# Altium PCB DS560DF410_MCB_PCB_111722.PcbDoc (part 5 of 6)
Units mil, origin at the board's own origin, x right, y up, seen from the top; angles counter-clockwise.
Board outline 5500 x 5000 mil, 6 copper layers (Top Layer, L2_GND1, L3_SIG1, L4_PWR1, L5_GND2, Bottom Layer), stack 61.748 mil thick; 297 components, 231 nets, 1236 pads, 998 vias.
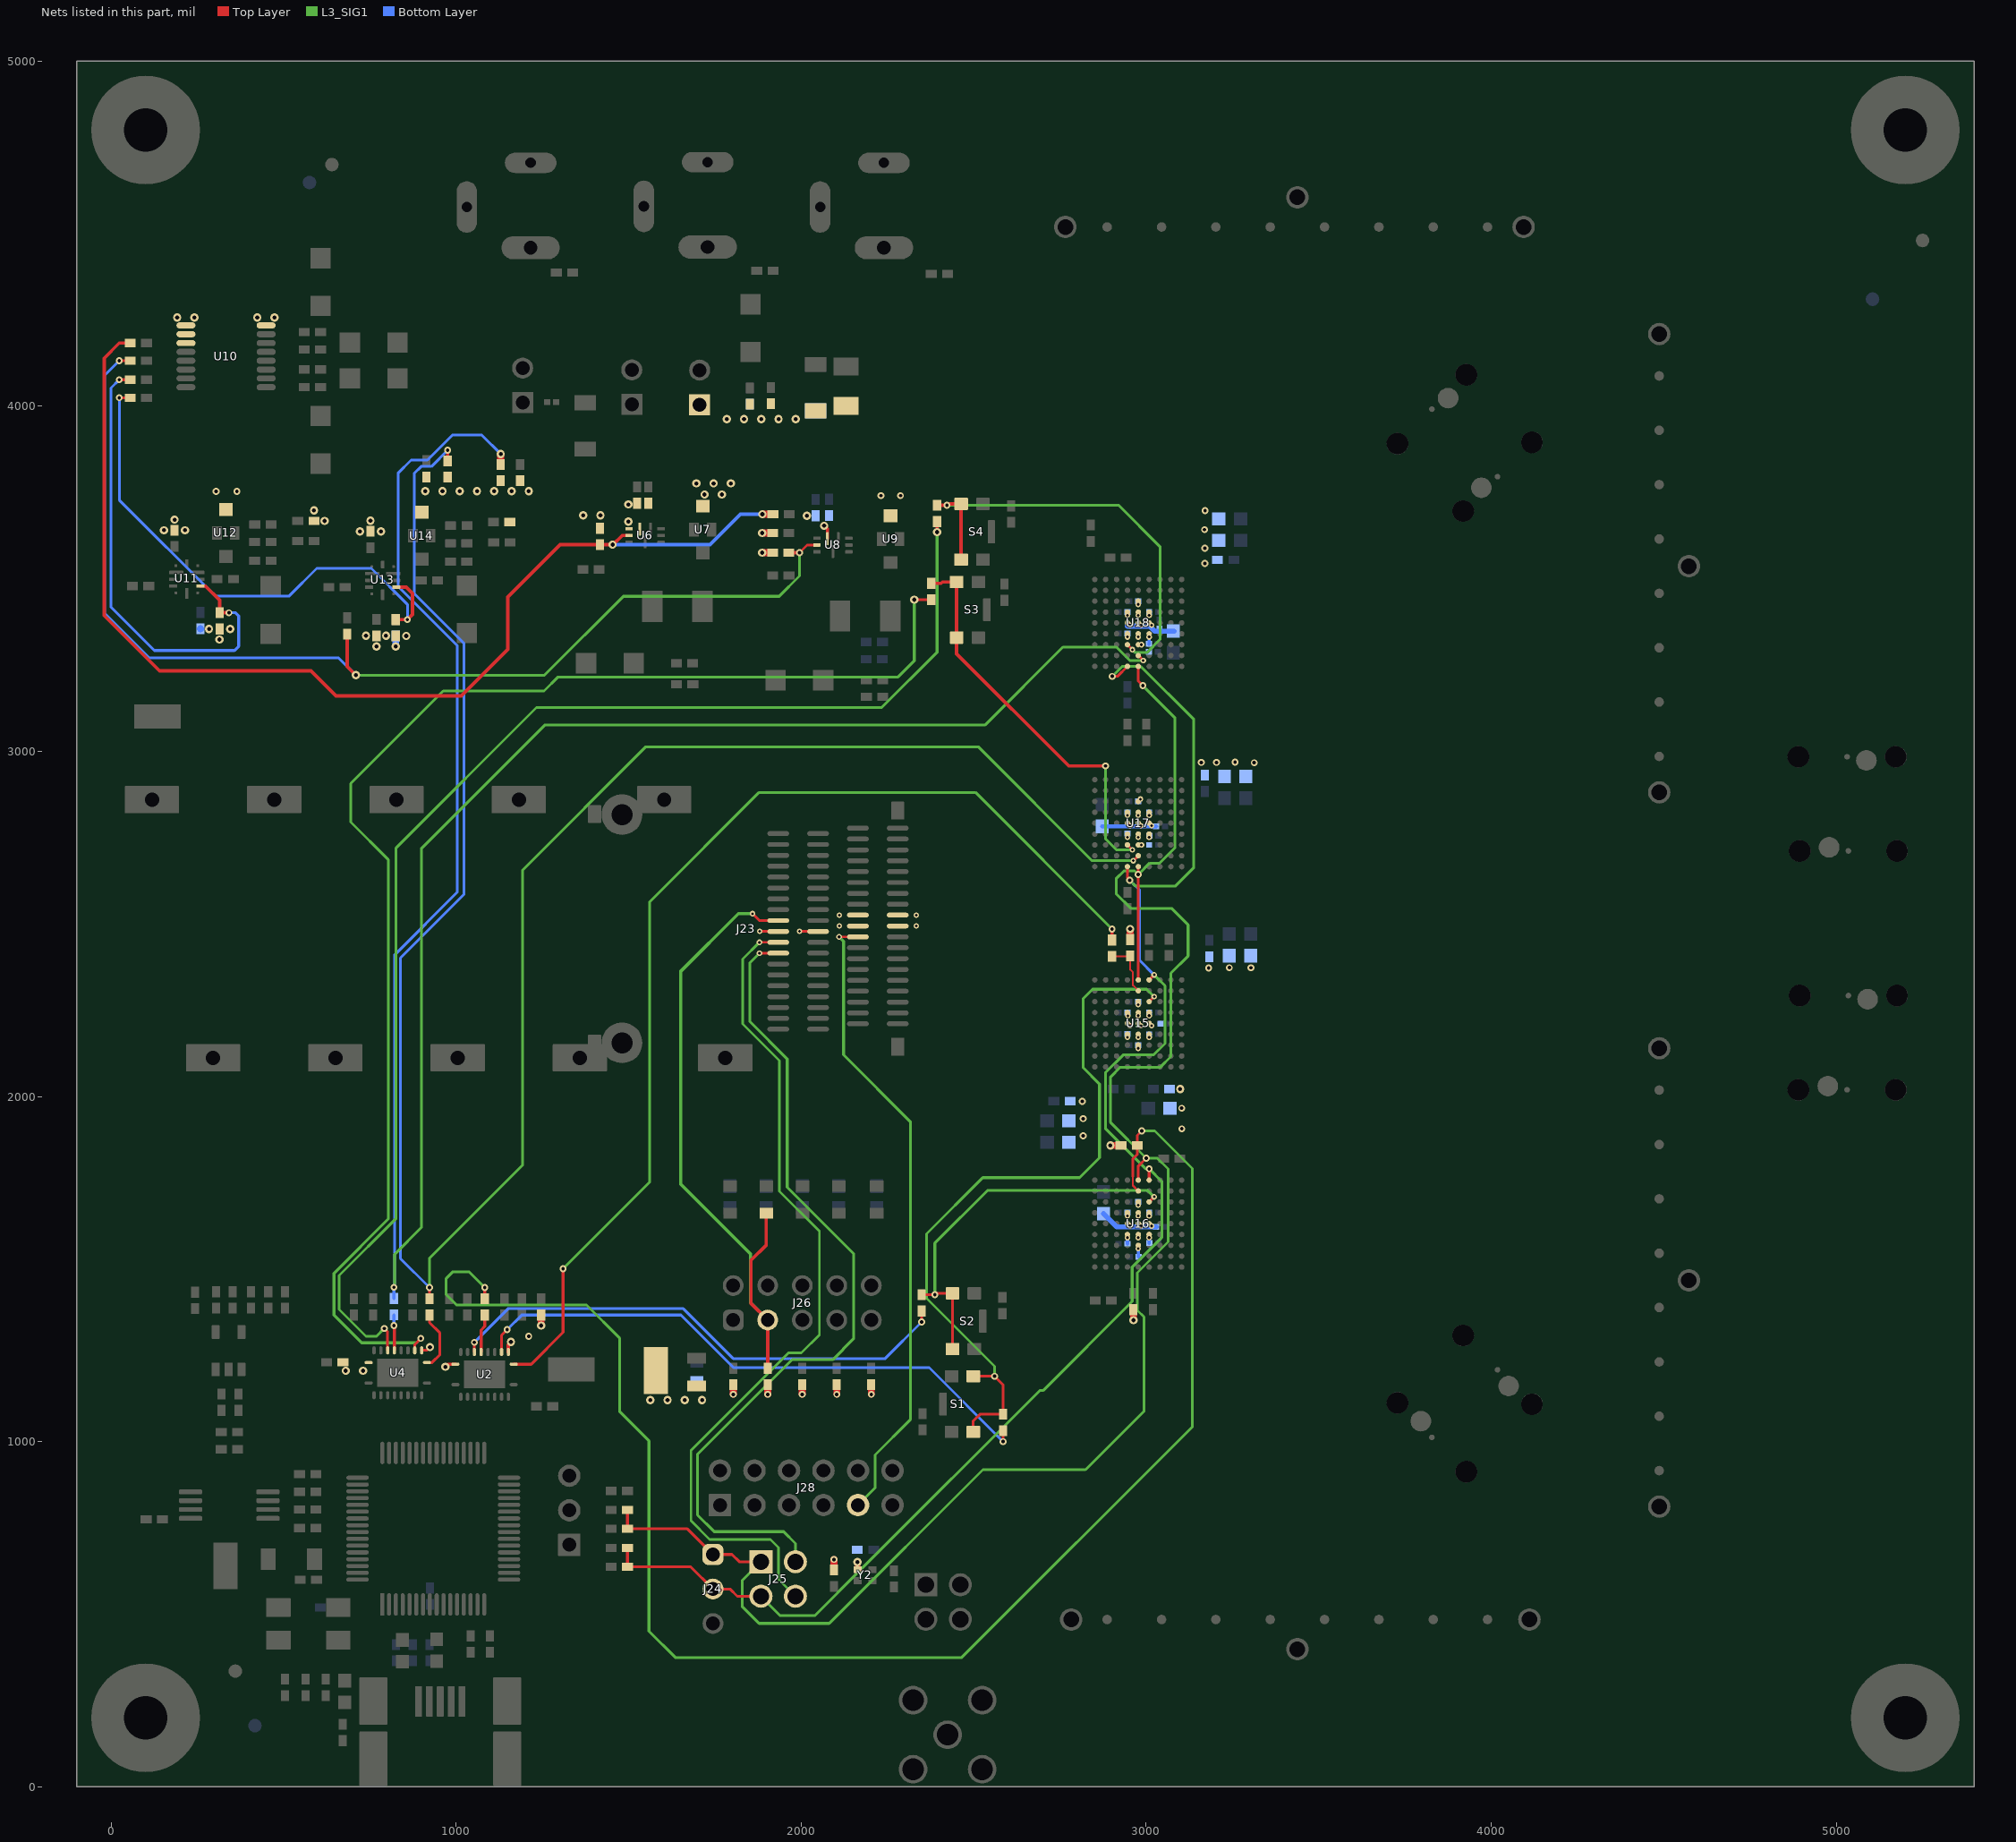
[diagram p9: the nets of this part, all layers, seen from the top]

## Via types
v1: diameter 20, hole 10, Top Layer to Bottom Layer, 380 vias
v2: diameter 24, hole 12, Top Layer to Bottom Layer, tented both sides, 226 vias
v3: diameter 20, hole 10, Top Layer to Bottom Layer, tented both sides, 162 vias
v4: diameter 14, hole 8.1, Top Layer to Bottom Layer, tented both sides, 88 vias
v5: diameter 16, hole 8.1, Top Layer to Bottom Layer, tented both sides, 84 vias
v6: diameter 16, hole 8, Top Layer to Bottom Layer, tented both sides, 34 vias
v7: diameter 15, hole 8.1, Top Layer to Bottom Layer, tented both sides, 16 vias
v8: diameter 19.68, hole 7.87, Top Layer to Bottom Layer, tented both sides, 8 vias

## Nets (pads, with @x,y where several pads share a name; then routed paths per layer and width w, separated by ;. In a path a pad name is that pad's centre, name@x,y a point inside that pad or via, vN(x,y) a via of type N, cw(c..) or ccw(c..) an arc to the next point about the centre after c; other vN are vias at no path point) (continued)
PG_1P2V_1: R18.1 R20.1 R27.1 U6.5 | length 3240.2
  Top Layer w10: R27.1@55.68,4182.86 23.9,4182.86 -20,4138.95 -20,3393.2 140.3,3232.9 579.6,3232.9 652.35,3160.15 1014.75,3160.15 1150.1,3295.5 1150.1,3447 1301.78,3598.68 R18.1@1417.2,3598.68 v2(1453.43,3598.68) 1454.85,3598.68 1481.39,3625.22 U6.5@1501.37,3625.22
  Top Layer w20: v2(1887.58,3687.1) R20.1@1918.14,3687.1
  Bottom Layer w10: v2(1453.43,3598.68) 1736.08,3598.68 1824.5,3687.1 v2(1887.58,3687.1)
PG_1P2V_2: R24.1 R26.1 R29.1 U8.5 | length 3274.7
  Top Layer w8: v3(23.9,4131.59) R29.1@55.68,4131.59 ; v3(1995.08,3575.36) 2017.36,3597.65 U8.5@2045.62,3597.65
  Top Layer w10: R26.1@684.55,3339.64 684.55,3245.55 v2(709.5,3220.6) ; R24.1@1964.51,3575.36 v3(1995.08,3575.36)
  L3_SIG1 w8: v2(709.5,3220.6) 1256.2,3220.6 1484.7,3449.1 1936.3,3449.1 1995.08,3507.88 v3(1995.08,3575.36)
  Bottom Layer w8: v3(23.9,4131.59) -18.45,4089.23 -18.45,3400.45 111.25,3270.75 659.35,3270.75 v2(709.5,3220.6)
PG_1P8V_1: R32.1 R40.1 U11.8 | length 1384
  Top Layer w8: v3(23.9,4076.59) R32.1@55.68,4076.59
  Top Layer w10: U11.8@258.91,3478.86 273.44,3478.86 314.48,3437.82 R40.1@314.48,3401.59 ; R40.1@314.28,3401.24 v3(341.64,3401.24)
  Bottom Layer w8: v3(23.9,4076.59) -0.22,4052.46 -0.22,3417.82 125.45,3292.15 357.91,3292.15 369.9,3304.14 369.9,3392.3 360.96,3401.24 v3(341.64,3401.24)
PG_1P8V_2: R34.1 R48.1 U13.8 | length 1568.5
  Top Layer w8: v3(23.9,4024.4) R34.1@55.68,4024.4
  Top Layer w10: R48.1@824.97,3381.68 v3(858.9,3381.68) 873.43,3396.2 873.43,3457.43 855.23,3475.62 U13.8@826.53,3475.62
  Bottom Layer w8: v3(23.9,4024.4) 23.9,3728.1 301.9,3450.1 516.38,3450.1 596.18,3529.9 754.53,3529.9 858.9,3425.52 v3(858.9,3381.68)
QSFP-DD_RESERVED: J23.66 J28.9 | length 1849.2
  Top Layer w7.3: v6(2109.87,2462.38) J23.66@2164.37,2462.38
  L3_SIG1 w8: v6(2109.87,2462.38) 2122.87,2449.37 2122.87,2120.55 2316.47,1926.95 2316.47,1063.53 2214.53,961.57 2214.53,865.92 J28.9@2164.72,816.12
QSFP-DD_SCL_HOST: J23.11 J25.4 | length 2465.9
  Top Layer w7.3: v6(1879.16,2446.63) J23.11@1933.66,2446.63
  L3_SIG1 w7.3: v6(1879.16,2446.63) 1830.56,2398.03 1830.56,2210.21 1937.18,2103.6 1937.18,1725.32 2053.03,1609.48 2053.03,1309.4 2000.74,1257.11 1963.56,1257.11 1680.75,974.3 1680.75,770.88 1734.91,716.72 1910.86,716.72 1934.45,693.12 1934.45,600.93 J25.4@1983.42,551.96
QSFP-DD_SDA_HOST: J23.12 J25.2 | length 2445.8
  Top Layer w7.3: v6(1879.16,2415.13) J23.12@1933.66,2415.13
  L3_SIG1 w8: v6(1879.16,2415.13) 1851.38,2387.35 1851.38,2217 1959.68,2108.7 1959.68,1736.98 2151.88,1544.78 2151.88,1297.62 2091.5,1237.25 1973.07,1237.25 1699.57,963.75 1699.57,787.55 1748.03,739.1 1949.18,739.1 1983.42,704.85 J25.2@1983.42,651.96
QSFP-DD_VCC_3P3V: C95.1 C96.1 J23.10 J23.29 J23.30 J23.48 J23.67 J23.68 R94.2 R95.2 R96.2 R97.2 R98.2 TP3.1 | length 249.6
  Top Layer w8: v6(1879.65,2478.13) J23.10@1933.66,2478.13 ; v6(1995,2478.13) J23.48@2049.02,2478.13
  Top Layer w20: v3(1803.16,1136.92) R96.2@1803.16,1165.24 ; v3(1903.16,1136.92) R94.2@1903.16,1165.24 ; v3(2003.16,1136.92) R97.2@2003.16,1165.24 ; v3(2103.16,1136.92) R98.2@2103.16,1165.24 ; v3(2203.16,1136.92) R95.2@2203.16,1165.24
  other v2: 1562.8,1120.68 1612.8,1120.68 1662.8,1120.68 1712.8,1120.68
  other v6: 2110.35,2493.87 2333.74,2493.87 2110.35,2525.37 2333.74,2525.37
READ_EN_N_1: R55.1 R56.1 U15.E8 | length 164
  Top Layer w5: R56.1@2900.93,2406.01 2952.08,2406.01 R55.1@2953.46,2407.39 2953.46,2367.12 2961.25,2359.32 2961.25,2348.69 2961.25,2322 U15.E8@2977,2306.25
READ_EN_N_1_LS: R56.2 U2.1 | length 3199.1
  Top Layer w8: U2.1@1167.1,1224.18 1217.61,1224.18 1310,1316.57 v3(1310,1500.7) ; R56.2@2900.93,2453.26 v3(2900.93,2485.03)
  L3_SIG1 w8: v3(1310,1500.7) 1560.95,1751.65 1560.95,2563.58 1878.07,2880.7 2505.26,2880.7 v3(2900.93,2485.03)
READ_EN_N_2: R67.1 R68.1 U16.E8 | length 4672.1
  Top Layer w6: 2961.25,1768.57 2961.25,1741.88 U16.E8@2977,1726.13
  Top Layer w8: R68.1@1083.06,1414.04 v3(1083.06,1446.33) ; 2961.25,1768.57 2961.25,1819.23 2973.96,1831.93 R67.1@2973.96,1858.12 2973.96,1887.13 v3(2986.93,1900.1)
  L3_SIG1 w8: v3(1083.06,1446.33) 1037.13,1492.25 990.78,1492.25 971.2,1472.68 971.2,1425.79 1000.99,1396 1377.9,1396 1473.5,1300.4 1473.5,1087.7 1559,1002.2 1559,450.6 1635.2,374.4 2465.5,374.4 3133.48,1042.38 3133.48,1791.52 3024.9,1900.1 v3(2986.93,1900.1)
READ_EN_N_2_LS: R68.2 U2.6 | length 111.5
  Top Layer w8: U2.6@1072.61,1259.61 1072.61,1323.46 1083.06,1333.91 R68.2@1083.06,1366.79
READ_EN_N_3: R77.1 R78.1 U17.E8 | length 6113.8
  Top Layer w8: R78.1@922.91,1414.04 v3(922.91,1446.33) ; v6(2962.51,2682.9) U17.E8@2977,2697.39
  Top Layer w10: R77.1@975.5,3841.62 v3(975.5,3872.19)
  L3_SIG1 w8: v3(922.91,1446.33) 922.91,1531.41 1192.54,1801.04 1192.54,2655.74 1549.95,3013.15 2513.1,3013.15 2843.35,2682.9 v6(2962.51,2682.9)
  Bottom Layer w8: v3(922.91,1446.33) 838.75,1530.49 838.75,2401.15 1022.95,2585.35 1022.95,3312.93 878.5,3457.38 878.5,3805.1 898.7,3825.3 928.61,3825.3 v3(975.5,3872.19)
READ_EN_N_3_LS: R78.2 U4.1 | length 174.5
  Top Layer w8: U4.1@915.66,1228.96 930.31,1228.96 953.2,1251.85 953.2,1314.5 922.91,1344.79 R78.2@922.91,1366.79
READ_EN_N_4: R87.1 R88.1 U18.E8 | length 6608.6
  Top Layer w8: U18.E8@2977,3277.51 v6(2991.49,3263.02)
  Top Layer w20: R87.1@1129.37,3831.01 v2(1129.37,3861.57)
  L3_SIG1 w8: v3@822.27,1446.33 822.27,1543.28 899.1,1620.11 899.1,2717.99 1256.91,3075.8 2532.4,3075.8 2758.4,3301.8 2913.6,3301.8 2952.38,3263.02 v6(2991.49,3263.02)
  Bottom Layer w8: R88.1@819.9,1414.62 v3(819.9,1446.91) ; v3@822.27,1446.33 822.27,2410.72 1003.53,2591.98 1003.53,3306.57 831.8,3478.3 831.8,3805.7 869.9,3843.8 916.9,3843.8 989.2,3916.1 1074.85,3916.1 v2(1129.37,3861.57)
READ_EN_N_4_LS: R88.2 U4.6 | length 101.3
  Top Layer w8: U4.6@821.17,1264.39 v3@821.17,1334.76
  Bottom Layer w8: v3(819.9,1336.44) R88.2@819.9,1367.38
RESET_N_1: R59.1 S1.1 S1.2 U15.F7 | length 2122.5
  Top Layer w8: S1.2@2498.76,1027.96 2498.76,1059.91 2518,1079.15 R59.1@2585.33,1079.15 2585.33,1164.44 v3(2560.4,1189.38) S1.1@2498.76,1189.38 ; U15.F7@3008.5,2274.76 v6(3022.99,2289.25)
  L3_SIG1 w8: v3(2560.4,1189.38) 2560.4,1218.28 2363.43,1415.25 2363.43,1601.82 2526.3,1764.7 2807,1764.7 2864.6,1822.3 2864.6,2036.15 2817.3,2083.45 2817.3,2283.7 2844.3,2310.7 3001.54,2310.7 v6(3022.99,2289.25)
RESET_N_1_LS: R59.2 U2.3 | length 1710.2
  Top Layer w8: U2.3@1131.67,1259.61 1131.67,1308.17 v3(1147.9,1324.4) ; v3(2585.33,1000.13) R59.2@2585.33,1031.91
  Bottom Layer w8: v3(1147.9,1324.4) 1190.29,1366.79 1651.66,1366.79 1804.1,1214.35 2371.12,1214.35 v3(2585.33,1000.13)
RESET_N_2: R70.1 S2.1 S2.2 U16.F7 | length 1128.9
  Top Layer w8: R70.1@2349.3,1425.62 v3(2387.42,1425.62) 2390.9,1429.1 2438.27,1429.1 S2.2@2438.74,1429.56 S2.1@2438.74,1268.15 ; U16.F7@3008.5,1694.64 v6(3022.99,1709.13)
  L3_SIG1 w8: v3(2387.42,1425.62) 2387.42,1575.22 2539.77,1727.57 3004.55,1727.57 v6(3022.99,1709.13)
RESET_N_2_LS: R70.2 U2.7 | length 1500.2
  Top Layer w8: U2.7@1052.93,1259.61 v3(1052.93,1287.57) ; v3(2349.3,1346.6) R70.2@2349.3,1378.37
  Bottom Layer w8: v3(1052.93,1287.57) 1150.51,1385.15 1658.5,1385.15 1802.88,1240.78 2243.48,1240.78 v3(2349.3,1346.6)
RESET_N_3: R80.1 S3.1 S3.2 U17.F7 | length 1168.5
  Top Layer w8: U17.F7@2945.5,2728.89 v6(2960,2714.4)
  Top Layer w10: R80.1@2377.07,3486.69 2405.63,3486.69 2409.58,3490.64 S3.2@2446.93,3490.64 ; S3.2@2450.64,3490.64 S3.1@2450.64,3329.22 2450.64,3282.51 2775.62,2957.52 v3(2881.87,2957.52)
  L3_SIG1 w8: v3(2881.87,2957.52) 2881.87,2746.39 2913.86,2714.4 v6(2960,2714.4)
RESET_N_3_LS: R80.2 U4.3 | length 3990.1
  Top Layer w8: U4.3@880.23,1264.39 880.23,1281.33 v3(897.84,1298.94) v3@898.88,1299.98 ; v2(2327.85,3439.45) R80.2@2377.07,3439.45
  L3_SIG1 w8: v3(897.84,1298.94) 885.3,1286.4 726.6,1286.4 646.2,1366.8 646.2,1487.66 803.15,1644.61 803.15,2686.45 694.8,2794.8 694.8,2906.8 962.6,3174.6 1254.93,3174.6 1295.62,3215.3 2280.97,3215.3 2327.85,3262.18 v2(2327.85,3439.45)
RESET_N_4: R90.1 S4.1 S4.2 U18.F7 | length 1289.2
  Top Layer w8: U18.F7@2945.5,3309.01 v6(2960,3294.51)
  Top Layer w10: R90.1@2393.85,3712.82 v3(2422.42,3712.82) 2426.36,3716.76 S4.2@2463.72,3716.76 S4.1@2463.72,3555.35
  L3_SIG1 w8: v3(2422.42,3712.82) 2920.53,3712.82 3039.99,3593.35 3039.99,3323.82 3002.2,3286.02 2968.49,3286.02 v6(2960,3294.51)
RESET_N_4_LS: R90.2 U4.7 | length 3825.9
  Top Layer w8: v3(791.72,1327.65) 801.49,1317.89 U4.7@801.49,1264.39
  Top Layer w10: v2(2393.85,3635.01) R90.2@2393.85,3665.57
  L3_SIG1 w8: v3(791.72,1327.65) 769.22,1305.15 738.9,1305.15 661.2,1382.85 661.2,1481.45 826.2,1646.45 826.2,2720 1232.9,3126.7 2233.5,3126.7 2393.85,3287.05 v2(2393.85,3635.01)
ResetL: D11.2 J23.9 J26.3 R94.1 | length 1962.7
  Top Layer w7.3: v6(1859.16,2529.62) 1879.16,2509.62 J23.9@1933.66,2509.62
  Top Layer w9.4: D11.2@1899.09,1661.5 1899.09,1569.59 1854.15,1524.65 1854.15,1401.16 J26.3@1903.16,1352.15 R94.1@1903.16,1212.48
  L3_SIG1 w9.4: v6(1859.16,2529.62) 1817.95,2529.62 1651.4,2363.07 1651.4,1745.4 1810.5,1586.3 1853.1,1543.7 1853.1,1402.21 J26.3@1903.16,1352.15
SCLK_I2C: J24.2 J25.3 R1.1 R2.1 U15.F9 U16.F9 U17.F9 U18.F9 | length 4555.5
  Top Layer w8: R2.1@1496.62,692.13 R1.1@1496.62,637.13 1680.28,637.13 J24.2@1744.46,572.95 1794.03,572.95 1815.02,551.96 J25.3@1883.42,551.96 ; v3(2901.62,3217.2) 2916.69,3217.2 U18.F9@2945.5,3246.02 ; U17.F9@2945.5,2665.9 2945.5,2633.22 v3(2952.32,2626.4) ; U16.F9@3008.5,1757.63 v3(3008.5,1790.43) ; U15.F9@3008.5,2337.75 v6(3022.99,2352.24)
  L3_SIG1 w8: J25.3@1883.42,551.96 1939.68,495.7 2039.5,495.7 2172.47,628.67 2172.54,628.67 2185.43,641.56 2185.43,641.63 2691.68,1147.88 2701.07,1147.88 2959.25,1406.05 2959.25,1505.45 3045.18,1591.38 3045.18,1753.75 v3(3008.5,1790.43) 2998.47,1790.43 2881.85,1907.05 2881.85,2068.85 2934.2,2121.2 3022.3,2121.2 3054.35,2153.25 3054.35,2320.88 v6(3022.99,2352.24) ; v3(2901.62,3217.2) 2930.05,3245.62 2983.43,3245.62 2984.04,3245.02 2985.26,3245.02 3137.8,3092.48 3137.8,2663.07 3083.68,2608.95 2969.77,2608.95 v3(2952.32,2626.4)
  Bottom Layer w8: v3(2952.32,2626.4) 2981.1,2597.62 2981.1,2394.13 v6(3022.99,2352.24)
SDATA_I2C: J24.1 J25.1 R3.1 R5.1 U15.E9 U16.E9 U17.E9 U18.E9 | length 5251.7
  Top Layer w8: R5.1@1496.62,802.13 R3.1@1496.62,747.13 1670.28,747.13 J24.1@1744.46,672.95 1799.58,672.95 1820.57,651.96 J25.1@1883.42,651.96 ; U16.E9@2977,1757.63 2977,1798.4 v3(2999.9,1821.3) ; U15.E9@2977,2337.75 v3(2977,2643.1) U17.E9@2977,2665.9 ; U18.E9@2977,3246.02 2977,3203.3 v3(2990.18,3190.12)
  L3_SIG1 w8: J25.1@1883.42,651.96 1828.82,597.36 1828.82,522.62 1878.15,473.3 2081.3,473.3 2526.62,918.62 2824.12,918.62 2993.38,1087.88 2993.38,1361.2 2974.25,1380.32 2974.25,1489.28 3063.52,1578.55 3063.52,1790.04 3032.26,1821.3 v3(2999.9,1821.3) 2896.85,1924.35 2896.85,2056.75 2924.8,2084.7 3040.57,2084.7 3071.49,2115.61 3071.49,2357.02 3121.35,2406.89 3121.35,2497.12 3073.5,2544.98 2955.62,2544.98 2912.95,2587.65 2912.95,2631.23 2935.5,2653.77 2966.33,2653.77 v3(2977,2643.1) 3010.05,2676.15 3039.05,2676.15 3082.7,2719.8 3082.7,3097.6 v3(2990.18,3190.12)
VDD_1P2V_1: C50.1 C51.1 C52.1 C54.1 C55.1 C56.1 C57.1 C58.1 C59.1 C62.1 C63.1 C64.1 C65.1 C66.1 C67.1 C68.1 C69.1 C70.1 U7.3 U15.D4 U15.D6 U15.E3 U15.E4 U15.E6 U15.E7 U15.F4 U15.F6 U16.D4 U16.D6 U16.E3 U16.E4 U16.E6 U16.E7 U16.F4 U16.F6 | length 289.3
  Top Layer w10: v5@2945.5,1591.01 U16.D4@2945.5,1600.15 ; v5@2945.5,1654 U16.D6@2945.5,1663.14 ; v5@2945.5,2171.13 U15.D4@2945.5,2180.27 ; v5@2946.8,2234.03 U15.D6@2946.8,2243.18 ; v5@2977,1559.51 U16.E3@2977,1568.65 ; v5@2977,1591.01 U16.E4@2977,1600.15 ; v5@2977,1654 U16.E6@2977,1663.14 ; v5@2977,1685.5 U16.E7@2977,1694.64 ; v5@2977,2139.63 U15.E3@2977,2148.77 ; v5@2977,2171.13 U15.E4@2977,2180.27 ; v5@2977,2234.12 U15.E6@2977,2243.26 ; v5@2977,2265.61 U15.E7@2977,2274.76 ; v5@3008.5,1591.01 U16.F4@3008.5,1600.15 ; v5@3008.5,1654 U16.F6@3008.5,1663.14 ; v5@3008.5,2171.13 U15.F4@3008.5,2180.27 ; v5@3008.5,2234.12 U15.F6@3008.5,2243.26
  Bottom Layer w10: C59.1@2945.18,2181.31 2945.18,2171.45 v5(2945.62,2171.01) ; C64.1@2945.5,1573.4 2945.62,1573.52 v5(2945.62,1590.89) ; C70.1@2945.5,1663.14 2945.5,1654 v5(2945.62,1653.88) ; C50.1@2945.5,2243.26 2946.92,2241.85 v5(2946.92,2233.92) ; C62.1@2977,1694.64 2977,1685.5 v5(2977.12,1685.38) ; C56.1@2977,2148.77 2977,2139.63 v5(2977.12,2139.51) ; C51.1@2977,2274.76 2977,2265.61 v5(2977.12,2265.5) ; v5(2977.12,1559.39) 2977.36,1559.15 2977.36,1536.14 C63.1@2978,1535.5 ; C65.1@3008.5,1663.14 3008.5,1654 v5(3008.61,1653.88) ; C54.1@3008.5,2180.27 3008.5,2171.13 v5(3008.61,2171.01) ; C52.1@3008.5,2243.26 3008.5,2234.12 v5(3008.61,2234) ; C67.1@3008.61,1575.22 v5(3008.61,1590.89)
  other v2: 1720.05,3744 1770.05,3744 1696.3,3776.15 1746.3,3776.15 1796.3,3776.15
  other v3: 2817.16,1886.1 2817.16,1935.71 2814.8,1986.1 3180.9,2372 3240.9,2373.1 3303.3,2372.8
  other v5: 2977.12,1590.89 2977.12,1653.88 2977.12,2171.01 2977.12,2234
VDD_1P2V_2: C73.1 C74.1 C75.1 C76.1 C77.1 C78.1 C79.1 C80.1 C81.1 C84.1 C85.1 C86.1 C87.1 C88.1 C89.1 C90.1 C91.1 C92.1 U9.3 U17.D4 U17.D6 U17.E3 U17.E4 U17.E6 U17.E7 U17.F4 U17.F6 U18.D4 U18.D6 U18.E3 U18.E4 U18.E6 U18.E7 U18.F4 U18.F6 | length 242.4
  Top Layer w10: v5@2945.5,2751.24 U17.F6@2945.5,2760.39 ; v5@2945.5,2814.24 U17.F4@2945.5,2823.38 ; v5@2945.5,3331.36 U18.F6@2945.5,3340.5 ; v5@2945.5,3394.35 U18.F4@2945.5,3403.5 ; U17.E7@2977,2728.89 v5@2986.14,2728.89 ; v5@2977,2751.24 U17.E6@2977,2760.39 ; v5@2977,2814.24 U17.E4@2977,2823.38 ; U17.E3@2977,2854.87 v5@2983.46,2861.34 ; U18.E7@2977,3309.01 v5@2986.14,3309.01 ; v5@2977,3331.36 U18.E6@2977,3340.5 ; v5@2977,3394.35 U18.E4@2977,3403.5 ; v5@2977,3425.85 U18.E3@2977,3434.99 ; v5@3008.5,2751.24 U17.D6@3008.5,2760.39 ; v5@3008.5,2814.24 U17.D4@3008.5,2823.38 ; v5@3008.5,3331.36 U18.D6@3008.5,3340.5 ; v5@3008.5,3394.35 U18.D4@3008.5,3403.5
  Bottom Layer w10: C78.1@2945.18,2761.43 2945.18,2751.57 v5(2945.62,2751.13) ; v5@2945.18,3331.69 C86.1@2945.18,3341.55 ; C74.1@2945.5,2823.38 2945.5,2814.24 v5(2945.62,2814.12) ; C89.1@2945.5,3403.5 2945.62,3403.38 v5(2945.62,3394.24) ; C84.1@2977,3434.99 2977,3425.85 v5(2977.12,3425.73) ; v5@2983.98,3311.4 v5(2986.26,3309.12) ; v5@2986.14,2728.89 v5(2986.26,2729.01) ; C85.1@3008.21,3311.4 3008.61,3311.81 v5(3008.61,3331.24) ; C81.1@3008.5,2760.39 3008.5,2751.24 v5(3008.61,2751.13) ; C76.1@3008.5,2823.38 3008.5,2814.24 v5(3008.61,2814.12) ; C92.1@3008.5,3397.67 C92.1@3008.5,3403.5
  other v3: 3312.9,2966.9 3159.6,2967.7 3203.8,2967.7 3257.6,2968.6 3169.9,3544.23 3169.9,3588.43 3169,3642.23 3170.7,3697.53 2231.23,3740.65 2287.9,3740.65
  other v5: 2977.12,2751.13 2977.12,2814.12 2983.46,2861.5 2945.62,3331.24 2977.12,3331.24 2977.12,3394.24 3008.61,3394.24
VDD_1P8V_1: C9.1 C53.1 C60.1 C61.1 C71.1 C72.1 R43.1 R54.2 R55.2 R58.2 R66.2 R67.2 U2.2 U2.10 U12.3 U15.D5 U15.E5 U15.F5 U16.D5 U16.E5 U16.F5 Y2.4 | length 407
  Top Layer w10: v2(968.75,1216.7) 976.22,1224.18 U2.10@997.81,1224.18 ; U2.2@1151.35,1259.61 1151.35,1281.19 v2(1158.83,1288.67)
  Top Layer w15: Y2.4@2163.43,628.57 v2(2163.43,650.67)
  Top Layer w20: v2(1246.32,1336.23) C9.1@1246.32,1366.79 ; R58.2@2095.29,627.97 v3(2095.29,658.54) ; v2(2896.15,1858.12) R67.2@2926.71,1858.12 ; R55.2@2953.46,2454.64 v2(2953.46,2485.2) ; v2(2962.95,1351.64) R66.2@2962.95,1382.21
  Bottom Layer w15: C72.1@2876.5,1660.5 2914.61,1622.39 2945.62,1622.39 2977.12,1622.39 3008.61,1622.39 C71.1@3028.5,1622.39
  other v2: 3098.42,2021.58 618.78,3667.48 588.22,3698.05
  other v3: 1210.43,1305.15 3103,1906.4 3102.87,1966 304.7,3752.9 364.9,3752.9
  other v5: 2952.69,1624.63 2984.18,1624.63 3015.68,1624.63 2952.69,2204.75 2984.18,2204.75 3015.68,2204.75
VDD_1P8V_2: C13.2 C82.1 C83.1 C93.1 C94.1 R51.1 R76.2 R77.2 R86.2 R87.2 U4.2 U4.10 U14.3 U17.D5 U17.E5 U17.F5 U18.D5 U18.E5 U18.F5 | length 325.7
  Top Layer w8: U4.2@899.91,1264.39 914.69,1264.39 v2(924.07,1273.78)
  Bottom Layer w12: C83.1@2872,2782.8 2977.12,2782.8 3008.43,2782.79 3008.61,2782.61 3008.8,2782.8 C82.1@3028.5,2782.8
  Bottom Layer w15: v5@2945.62,3362.74 2977.12,3362.74 3008.61,3362.74 3009.66,3362.74 3024.4,3348 C94.1@3080.5,3348
  other v2: 680.28,1205.3 730.28,1205.3 910.6,3753.68 960.6,3753.68 1010.6,3753.68 1060.6,3753.68 1110.6,3753.68 1160.6,3753.68 1210.6,3753.68
  other v5: 2952.69,2784.87 2984.18,2784.87 3015.68,2784.87 2952.69,3364.98 2984.18,3364.98 3015.68,3364.98
VDD_3p3V: C26.1 C27.1 C28.1 C29.1 C30.1 C32.1 C33.1 C36.1 C37.1 C40.1 C45.1 F1.1 J6.1 R15.2 R18.2 R21.1 R24.2 R31.1 R37.1 R40.2 R45.1 R48.2 U6.3 U6.4 U8.3 U10.1 U10.2 U10.3 U10.16 | length 133.7
  Top Layer w10: v2(2066.57,3653.48) 2076.14,3643.91 U8.3@2076.14,3616.35
  Top Layer w20: v2(1886.7,3575.36) R24.2@1917.27,3575.36 ; v2(1886.7,3632.35) R21.1@1917.27,3632.35
  Bottom Layer w20: C40.1@259.12,3354.97 C40.1@259.74,3354.35 ; v2(824.97,3303.87) C45.1@824.97,3334.43
  other v2: 769.4,3304.14 314.48,3323.79 855.53,3334.43 738.84,3334.7 796.96,3334.7 283.91,3354.35 345.04,3354.35 721.16,3637.29 782.29,3637.29 153.55,3640.53 214.67,3640.53 1499.6,3665.3 751.73,3667.85 184.11,3671.09 2016.57,3682.44 1368.18,3683.52 1418.18,3683.52 1499.6,3715.3 1784.53,3962.3 1834.52,3962.3 1884.53,3962.3 1934.53,3962.3 1984.53,3962.3 191.55,4256.7 241.55,4256.7 423.83,4256.7 473.83,4256.7
pads on no net: FID1.1 FID2.1 FID3.1 FID4.1 FID5.1 FID6.1 H1.1 H2.1 H3.1 H4.1 J2.4 J9. J10. J11.7 J11.8 J14. J15. J16.7 J16.8 J17. J18. J19.1 J19.2 J20. J21. J22.1 J22.2 J23.65 LBL1.0 SH-J1.0 U1.4 U3.19 U3.26 U3.27 U3.28 U3.29 U3.38 U3.39 U3.40 U3.41 U3.48 U3.52 U3.53 U3.54 U5.6 U5.7 U10.14 U10.15 U15.D2 U15.D3 U15.D7 U15.D8 U15.F3 U16.D2 U16.D3 U16.D7 U16.D8 U16.F3 U17.D2 U17.D3 U17.D7 U17.D8 U17.F3 U18.D2 U18.D3 U18.D7 U18.D8 U18.D9 U18.F3

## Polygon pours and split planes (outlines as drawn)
GND on L2_GND1 "L2_GND1-GND 1" (solid, remove dead copper, pour order 172): 5249.82,4965.25 60.12,4965.25 -50.7,4854.43 -50.7,135.88 36.58,48.6 5109.05,48.6 5361.7,301.25 5361.7,4853.38
GND on Top Layer "L5_GND2-GND" (solid, remove dead copper, pour order 284): 5361.7,4853.38 5249.82,4965.25 60.12,4965.25 -50.7,4854.43 -50.7,135.88 36.58,48.6 5109.05,48.6 5361.7,301.25
NetD9_2 on Top Layer "NONET_L01_P-001" (solid, remove dead copper, pour order 267): 999.81,3449.54 1064.96,3449.54 1068.2,3452.78 1068.2,3559.6 1062.7,3565.1 1017.6,3565.1 1014.1,3561.6 1014.1,3527 997.7,3510.6 997.7,3451.65
VDD_1P8V_1 on Top Layer "NONET_L01_P-001" (solid, remove dead copper, pour order 56): 1147.04,1252.15 1147.04,1295.35 1175.16,1323.46 1214.01,1323.46 1222.5,1331.95 1222.5,1375.24 1232.77,1385.5 1260.74,1385.5 1269.47,1376.78 1269.47,1319.2 1197.44,1247.17 1151.35,1247.17 1151.35,1247.6 1146.8,1252.15
1P2V_CON on Top Layer "NONET_L01_P-001" (solid, remove dead copper, pour order 64): 2381.51,4507.3 2394.91,4493.9 2394.91,4377.5 2384.51,4367.1 2162.31,4367.1 2131.61,4397.79 2131.61,4494.7 2144.22,4507.3
1P8V_CON on Top Layer "NONET_L01_P-001" (solid, remove dead copper, pour order 62): 1875.9,4507.3 1889.3,4493.9 1889.3,4377.5 1878.9,4367.1 1656.69,4367.1 1626,4397.79 1626,4494.7 1638.6,4507.3
3P3V_FTDI on Top Layer "NONET_L01_P-001" (solid, remove dead copper, pour order 50): 1240.02,1054.14 1208.14,1054.14 1174.08,1088.2 1174.08,1109.67 1166.25,1117.5 1149.69,1117.5 1145.52,1121.67 1145.52,1138.28 1148.23,1141 1236.5,1141 1251.6,1125.9 1251.6,1065.72
VDD_1P2V_1 on Top Layer "NONET_L01_P-001" (solid, pour order 70): 1673.43,3690.18 1786.34,3690.18 1812.93,3716.76 1812.93,3789.37 1804,3798.3 1682.2,3798.3 1669.52,3785.62 1669.52,3694.16 1673.4,3690.28
VDD_1P8V_1 on Top Layer "NONET_L01_P-001" (solid, pour order 265): 360.4,3676.2 378.6,3694.4 378.6,3755.57 358.57,3775.6 304.33,3775.6 286.78,3758.05 286.78,3697.12 307.7,3676.2
VDD_1P2V_2 on Top Layer "NONET_L01_P-001" (solid, pour order 264): 2293.54,3663.61 2306.36,3676.43 2306.36,3754.24 2299.1,3761.5 2238.4,3761.5 2230.83,3761.5 2218.96,3749.62 2218.96,3681.57 2236.91,3663.61
VDD_1P8V_1 on Top Layer "NONET_L01_P-001" (solid, remove dead copper, pour order 263): 2082.7,612.8 2137.79,612.8 2143.69,618.7 2176.9,618.7 2181.3,623.1 2181.3,674.1 2163.47,691.93 2090.03,691.93 2072.1,674 2072.1,623.4
VDD_3p3V on Top Layer "TOP_LAYER_VDD_3P3V_P262" (solid, remove dead copper, pour order 262): 802.07,3350.95 860.45,3350.95 868.2,3343.2 868.2,3298.9 861.05,3291.75 803.92,3291.75 736.52,3291.75 726.42,3301.85 726.42,3340.55 736.82,3350.95
VDD_3p3V on Top Layer "TOP_LAYER_VDD_3P3V_P260" (solid, remove dead copper, pour order 260): 719.06,3621.04 784.31,3621.04 794.71,3631.44 794.71,3670.14 784.61,3680.24 717.21,3680.24 708.91,3671.94 708.91,3631.19
VDD_3p3V on Top Layer "TOP_LAYER_VDD_3P3V_P259" (solid, remove dead copper, pour order 259): 151.44,3624.28 216.69,3624.28 227.09,3634.68 227.09,3673.38 216.99,3683.48 149.59,3683.48 141.29,3675.18 141.29,3634.43
VDD_3p3V on Top Layer "TOP_LAYER_VDD_3P3V_P258" (solid, remove dead copper, pour order 258): 347.15,3370.6 281.9,3370.6 271.5,3360.2 271.5,3321.5 281.6,3311.4 349,3311.4 357.3,3319.7 357.3,3360.45
3P3V_CON on Top Layer "TOP_LAYER_3P3V_CON_P060" (solid, remove dead copper, pour order 60): 1084.1,4077.5 1247.9,4077.5 1307,4136.6 1307,4474.4 1285.1,4496.3 1140.9,4496.3 1122.8,4478.2 1122.8,4226 1066.6,4169.8 1066.6,4095
QSFP-DD_VCC_3P3V on Top Layer "Top Layer-QSFP-DD_VCC_3P3V 1" (solid, remove dead copper, pour order 268): 2336.5,2537.5 2103.3,2537.5 2092.3,2526.5 2092.3,2503.4 2078.8,2489.9 1875.4,2489.9 1868.4,2482.9 1868.4,2473.4 1876.3,2465.5 2090.6,2465.5 2108.3,2483.2 2337.2,2483.2 2343.4,2489.4 2343.4,2530.6
3P3V_VPHY on Top Layer "Top Layer-3P3V_VPHY" (solid, remove dead copper, pour order 255): 211.77,1477.77 250.24,1477.77 261.24,1466.77 261.24,1421.07 256.07,1415.9 211.9,1415.9 202.8,1425 202.8,1468.8
VDD_1P8V_1 on Top Layer "Top Layer-VDD_1P8V_1" (solid, remove dead copper, pour order 247): 622.6,3712.5 581.4,3712.5 570.4,3701.5 570.4,3655.8 573.9,3652.3 624.53,3652.3 634.7,3662.47 634.7,3700.4
1P8V_CON on Top Layer "Top Layer-1P8V_CON" (solid, remove dead copper, pour order 246): 511.2,3738.8 496.4,3753.6 456.8,3753.6 446.1,3742.9 446.1,3644.6 449.2,3641.5 479,3641.5 483.3,3645.8 483.3,3668.4 511.2,3696.3
GND on Top Layer "Top Layer-GND 4" (solid, remove dead copper, pour order 228): 1617.5,3770.98 1603.12,3785.35 1513.65,3785.35 1507.22,3778.93 1507.22,3749.62 1511.5,3745.35 1578.75,3745.35 1583.45,3740.65 1583.45,3690.18 1558.3,3665.02 1558.3,3626.5 1560.4,3624.4 1569.75,3624.4 1584.85,3639.5 1640.88,3639.5 1665.28,3615.1 1754.03,3615.1 1758.5,3619.57 1758.5,3661.35 1752.6,3667.25 1668.85,3667.25 1617.5,3718.6
3P3V_CON on Top Layer "Top Layer-3P3V_CON" (solid, remove dead copper, pour order 245): 2216.2,4154.7 2098.4,4154.7 2093.7,4150 2093.7,4081.6 2098.5,4076.8 2220,4076.8 2227.9,4084.7 2227.9,4143
GND on Top Layer "Top Layer-GND 11" (solid, remove dead copper, pour order 244): 1143.09,1235.57 1141.67,1236.99 1022.64,1236.99 1019.87,1234.22 1019.87,1182.77 1010.69,1173.59 987.94,1173.59 984.57,1170.22 984.57,1155.04 986.64,1152.97 1141.94,1152.97 1143.09,1154.12
GND on Top Layer "Top Layer-GND 13" (solid, remove dead copper, pour order 243): 632.05,281.95 551.38,281.95 548.23,278.8 548.23,228.72 554.7,222.25 624.6,222.25 635,232.64 635,279
QSFP-DD_VCC_3P3V on Top Layer "Top Layer-QSFP-DD_VCC_3P3V" (solid, remove dead copper, pour order 58): 1550.47,1103.93 2212.86,1103.93 2229.8,1120.87 2229.8,1166.95 2215.18,1181.58 1629.57,1181.58 1617.85,1193.3 1617.85,1273.5 1614.72,1276.62 1544.03,1276.62 1540.95,1273.55 1540.95,1113.45
GND on Top Layer "Top Layer-GND" (solid, remove dead copper, pour order 106): 1080.28,345.75 1090.65,356.12 1127.88,356.12 1140.93,369.18 1140.93,407.62 1129.1,419.45 1086.72,419.45 1083.47,422.7 1083.47,453.6 1087.7,457.82 1182.45,457.82 1206.7,433.58 1206.7,393.62 1206.7,8.6 1199.38,1.28 1104.47,1.28 1098.38,7.38 1098.38,185.85 1086.65,197.57 1010,197.57 1004.8,202.78 1004.8,293.9 1010.8,299.9 1063.5,299.9 1080.28,316.68
GND on Top Layer "Top Layer-GND 1" (solid, remove dead copper, pour order 236): 2601.45,3455.23 2502.25,3455.23 2491.12,3444.1 2491.12,3381.75 2499.62,3373.25 2594.1,3373.25 2603.98,3383.12 2603.98,3452.7
GND on Top Layer "Top Layer-GND 2" (solid, remove dead copper, pour order 230): 2539.4,3603.48 2543.39,3599.49 2615.55,3599.49 2624.02,3607.96 2624.02,3677.04 2621.02,3680.04 2545.66,3680.04 2539.4,3673.77
GND on Top Layer "Top Layer-GND 5" (solid, remove dead copper, pour order 198): 2997.13,2438.42 3077.56,2438.42 3080.71,2441.57 3080.71,2491.65 3074.23,2498.12 2999.1,2498.12 2994.15,2493.18 2994.15,2441.4
GND on Top Layer "Top Layer-GND 6" (solid, remove dead copper, pour order 184): 209.6,3153.47 198.27,3164.8 72.23,3164.8 62.92,3155.5 62.92,3067.12 67.75,3062.3 203.88,3062.3 209.6,3068.02
GND on Top Layer "Top Layer-GND 7" (solid, remove dead copper, pour order 124): 2514.57,1314.9 2522.19,1307.29 2590.57,1307.29 2599.04,1315.76 2599.04,1384.84 2596.04,1387.84 2519.89,1387.84 2514.57,1382.52
GND on Top Layer "Top Layer-GND 8" (solid, remove dead copper, pour order 116): 2422.7,1141.68 2420,1144.37 2344.68,1144.38 2336.2,1135.9 2336.2,1066.82 2339.2,1063.82 2416.2,1063.82 2422.7,1070.33
GND on Top Layer "Top Layer-GND 9" (solid, remove dead copper, pour order 104): 799.32,320.25 721.3,320.25 715.32,314.28 715.32,160.18 707.07,151.93 660.6,151.93 657.88,149.2 657.88,5.57 662.1,1.35 800.68,1.35 805.3,5.97 805.3,314.28
GND on Top Layer "Top Layer-GND 11" (solid, remove dead copper, pour order 94): 891.65,1240.35 890.22,1241.78 771.2,1241.78 768.43,1239 768.43,1187.55 759.25,1178.38 736.5,1178.38 733.12,1175 733.12,1159.82 735.2,1157.75 890.5,1157.75 891.65,1158.9
GND on Top Layer "Top Layer-GND 12" (solid, remove dead copper, pour order 92): 883.3,4220.62 806.55,4220.62 799.18,4213.25 799.18,4051.52 808.05,4042.65 882.45,4042.65 890.3,4050.5 890.3,4213.62
GND on Top Layer "Top Layer-GND 13" (solid, remove dead copper, pour order 90): 290.09,1416.53 364.69,1416.53 367.84,1419.68 367.84,1469.76 361.37,1476.23 294.94,1476.23 287.37,1468.66 287.37,1419.26
GND on Top Layer "Top Layer-GND 14" (solid, remove dead copper, pour order 88): 518.1,1404.47 443.5,1404.47 440.35,1401.32 440.35,1351.25 446.82,1344.77 513.25,1344.77 520.82,1352.35 520.82,1401.75
GND on Top Layer "Top Layer-GND 15" (solid, remove dead copper, pour order 86): 411.75,1101.1 404.15,1108.7 308.7,1108.7 303.3,1103.3 303.3,1072.8 306.9,1069.2 338.78,1069.2 347.72,1060.25 347.72,967.18 352.88,962.03 399.12,962.02 411.75,974.65
GND on Top Layer "Top Layer-GND 16" (solid, remove dead copper, pour order 84): 476.18,695.95 409.9,695.95 401.22,687.27 401.22,511.62 423.85,489 518.67,489 521.8,492.12 521.8,530.52 565.4,574.12 565.4,611.67 563.9,613.18 496.68,613.18 482.3,627.55 482.3,689.82
GND on Bottom Layer "L5_GND2-GND" (solid, remove dead copper, pour order 283): 5361.7,4853.38 5249.82,4965.25 60.12,4965.25 -50.7,4854.43 -50.7,135.88 36.58,48.6 5109.05,48.6 5361.7,301.25
VDD_1P2V_1 on Bottom Layer "NONET_L01_P-001" (solid, remove dead copper, pour order 269): 2937.1,1602.4 3012.5,1602.4 3020.3,1594.6 3020.3,1532.6 3008.5,1520.8 2969.4,1520.8 2965.67,1524.53 2965.67,1549.73 2953,1562.4 2937.3,1562.4 2934.48,1565.22 2934.48,1599.78
VDD_1P2V_2 on Bottom Layer "NONET_L01_P-001" (solid, remove dead copper, pour order 280): 2935.93,3412.83 2940.9,3417.8 2963.95,3417.8 2967.8,3421.65 2967.8,3443.1 2968.9,3444.2 2998.65,3444.2 3018.3,3424.55 3018.3,3394.24 3014.14,3390.07 2986.17,3390.07 2981.6,3385.5 2938.73,3385.5 2935.93,3388.3
VDD_1P2V_2 on Bottom Layer "NONET_L01_P-001" (solid, remove dead copper, pour order 279): 2934.78,3349.1 2936.68,3351 3002.2,3351 3018.15,3335.05 3018.15,3280.49 3015.75,3278.09 2997.81,3278.09 2963.7,3312.2 2952.8,3323.1 2942.68,3323.1 2934.78,3331
VDD_1P8V_2 on Bottom Layer "NONET_L01_P-001" (solid, remove dead copper, pour order 278): 2942.09,3354.8 2935.09,3361.8 2935.09,3364.67 2944.28,3373.86 2987.26,3373.86 3018.29,3373.86 3024.81,3367.44 3098.43,3367.44 3098.43,3328.73 3096.4,3326.7 3059.7,3326.7 3047.4,3339 3020.03,3339 3004.23,3354.8
VDD_1P2V_2 on Bottom Layer "NONET_L01_P-001" (solid, remove dead copper, pour order 277): 3016.34,2770.1 3019.24,2767.2 3019.24,2724.74 3013.7,2719.2 2983.84,2719.2 2973,2730.04 2973,2734.9 2965.2,2742.7 2941.5,2742.7 2934.78,2749.42 2934.78,2769.48 2935.4,2770.1
VDD_1P2V_2 on Bottom Layer "NONET_L01_P-001" (solid, remove dead copper, pour order 275): 2935.18,2812.35 2941.93,2805.6 3014.2,2805.6 3019.24,2810.64 3019.24,2848.86 2997.72,2870.38 2970.87,2870.38 2966.6,2866.11 2966.6,2842.8 2958.22,2834.42 2936.68,2834.42 2935.18,2832.93
VDD_1P8V_2 on Bottom Layer "NONET_L01_P-001" (solid, remove dead copper, pour order 274): 2852.2,2763.4 2852.2,2801.9 2853.7,2803.4 2890.8,2803.4 2902.7,2791.5 3038.02,2791.5 3039.99,2789.53 3039.99,2776.29 3037.6,2773.9 2903.04,2773.9 2889.53,2760.39 2855.21,2760.39
VDD_1P2V_1 on Bottom Layer "NONET_L01_P-001" (solid, remove dead copper, pour order 273): 2935.79,2191.1 3016.7,2191.1 3019.24,2188.56 3019.24,2143.06 3006.98,2130.8 2971.2,2130.8 2966.3,2135.7 2966.3,2159.5 2963.9,2161.9 2939.58,2161.9 2933.77,2167.71 2933.77,2189.08
VDD_1P2V_1 on Bottom Layer "NONET_L01_P-001" (solid, remove dead copper, pour order 272): 3017.54,2228.76 3017.54,2254.86 2987.74,2284.66 2968.86,2284.66 2966.6,2282.4 2966.6,2261.2 2957.7,2252.3 2935.87,2252.3 2934.48,2250.91 2934.48,2229.64 2939.25,2224.87 3013.65,2224.87 3017.54,2228.76
VDD_1P2V_1 on Bottom Layer "NONET_L01_P-001" (solid, remove dead copper, pour order 271): 2935.79,1648.66 2940.36,1644.09 3014.4,1644.09 3020.3,1649.99 3020.3,1673.72 3016.41,1677.61 3000.83,1677.61 2987.2,1691.24 2987.2,1703.2 2985.4,1705 2967.1,1705 2964.3,1702.2 2964.3,1679.7 2959.34,1674.74 2934.58,1674.74 2932.96,1673.12 2932.96,1651.59 2935.79,1648.76
VDD_1P8V_1 on Bottom Layer "NONET_L01_P-001" (solid, remove dead copper, pour order 270): 3037.5,1614.3 3037.5,1632.73 3034.48,1635.75 2921.15,1635.75 2904.48,1652.42 2904.48,1673.12 2895.5,1682.1 2854.34,1682.1 2851.13,1678.89 2851.13,1640.17 2854.2,1637.1 2877.83,1637.1 2903.53,1611.4 3034.6,1611.4
VDD_1P8V_1 on Bottom Layer "NONET_L01_P-001" (solid, pour order 80): 2170.6,637.3 2186.2,652.9 2186.2,725.8 2180.4,731.6 2075.8,731.6 2065.7,721.5 2065.8,721.4 2065.8,640.7 2069.2,637.3
VDD_1P2V_2 on Bottom Layer "NONET_L01_P-001" (solid, pour order 82): 3165.6,3528.83 3210.7,3528.83 3223.65,3541.77 3223.65,3584.26 3231.58,3592.19 3231.58,3694.04 3214.27,3711.36 3162.82,3711.36 3155.5,3704.04 3155.5,3538.93
VDD_1P2V_2 on Bottom Layer "NONET_L01_P-001" (solid, pour order 110): 3144.2,2972 3144.2,2926.9 3157.15,2913.95 3199.63,2913.95 3207.56,2906.03 3309.42,2906.03 3326.73,2923.34 3326.73,2974.79 3319.42,2982.1 3154.3,2982.1
VDD_1P2V_1 on Bottom Layer "NONET_L01_P-001" (solid, pour order 114): 2835.57,2007.04 2835.96,1849.07 2822.55,1835.67 2757.14,1835.67 2751.45,1841.36 2751.45,1999.65 2769.46,2017.66 2824.95,2017.66
VDD_1P2V_1 on Bottom Layer "NONET_L01_P-001" (solid, pour order 257): 3168.2,2425.2 3172,2429 3323.9,2429 3329.56,2423.34 3329.56,2363.06 3318.5,2352 3172.52,2352 3165.2,2359.32 3165.2,2422.1 3168.3,2425.2
VDD_3p3V on Bottom Layer "NONET_L01_P-001" (solid, remove dead copper, pour order 256): 244.45,3326.3 261.65,3309.1 342,3309.1 359.8,3326.9 359.8,3361.5 349,3372.3 244.45,3372.3
NetC46_1 on Bottom Layer "NONET_L01_P-001" (solid, pour order 254): 997.7,3672 1002.4,3667.3 1002.4,3535.9 995.6,3529.1 955.3,3529.1 946.1,3538.3 946.1,3662.8 955.3,3672
VDD_1P8V_1 on Bottom Layer "NONET_L01_P-001" (solid, pour order 253): 3046.7,2030.01 3046.7,1932.3 3053.24,1925.76 3053.24,1893.71 3056.8,1890.15 3105.85,1890.15 3114.97,1899.27 3114.97,2033.42 3105.29,2043.1 3059.79,2043.1
NetC38_1 on Bottom Layer "NONET_L01_P-001" (solid, pour order 252): 2217.9,3254.32 2217.9,3330.5 2220.5,3333.1 2284.2,3333.1 2292.16,3325.14 2292.16,3255.5 2283.65,3247 2225.22,3247
NetC41_1 on Bottom Layer "Bottom Layer-NetC41_1" (solid, remove dead copper, pour order 250): 429.9,3672.4 376.4,3672.4 366.8,3662.8 366.8,3546.3 375.2,3537.9 430.5,3537.9 433.1,3540.5 433.1,3669.2
NetC34_1 on Bottom Layer "Bottom Layer-NetC34_1" (solid, remove dead copper, pour order 249): 1719.1,3269.6 1671.4,3269.6 1668.5,3266.7 1668.5,3182.9 1677.38,3174.02 1723.42,3174.02 1732.3,3182.9 1732.3,3256.4
GND on Bottom Layer "Bottom Layer-GND 2" (solid, remove dead copper, pour order 130): 270.9,3433.52 172.01,3433.52 166.67,3428.19 166.67,3393.73 174.62,3385.77 271.62,3385.77 273.78,3387.93 273.78,3430.65
3P3V_FTDI on Bottom Layer "Bottom Layer-3P3V_FTDI" (solid, remove dead copper, pour order 218): 263.65,778.05 253.03,788.68 132.58,788.68 129.35,785.45 129.35,737.25 137.65,728.95 255.22,728.95 263.65,737.38
QSFP-DD_VCC_3P3V on Bottom Layer "Bottom Layer-QSFP-DD_VCC_3P3V" (solid, remove dead copper, pour order 194): 1549.75,1191.52 1540.95,1182.72 1540.95,1113.45 1550.48,1103.92 1723.2,1103.92 1731.46,1112.19 1731.46,1147.95 1731.45,1183.15 1723.07,1191.52 1683.82,1191.52
GND on Bottom Layer "Bottom Layer-GND" (solid, remove dead copper, pour order 150): 2114.22,3742.2 2107.95,3748.48 2012.55,3748.47 2007.82,3743.75 2007.82,3721.35 2016.8,3712.37 2108.22,3712.38 2114.22,3718.38
GND on Bottom Layer "Bottom Layer-GND 1" (solid, remove dead copper, pour order 148): 841.39,3405.78 808.57,3438.6 743,3438.6 734.32,3429.93 734.32,3379.77 749.28,3364.82 837.53,3364.82 841.39,3368.69
GND on Bottom Layer "Bottom Layer-GND 4" (solid, remove dead copper, pour order 126): 2243.53,1693.77 2238.72,1698.57 1773.55,1698.57 1771.8,1696.82 1771.8,1656.1 1774.62,1653.28 2239.05,1653.27 2243.53,1657.75
GND on Bottom Layer "Bottom Layer-GND 5" (solid, remove dead copper, pour order 118): 1061.5,381.72 1078.75,364.47 1129.18,364.47 1159.5,394.8 1194.65,394.8 1207.72,381.72 1207.72,235.18 1179.22,206.68 1040.47,206.68 1028.78,218.38 1028.78,320.45 1005.25,343.97 817.12,343.97 813.6,347.5 813.6,380.72 814.6,381.72
3P3V_VPHY on L3_SIG1 "L3_SIG1-3P3V_VPHY" (solid, remove dead copper, pour order 144): 517.07,1518.72 250.22,1518.72 199,1467.5 199,1356.05 250.2,1304.85 392.8,1304.85 439.97,1257.68 439.97,1078.9 413.82,1052.75 286.97,1052.75 269.15,1034.93 269.15,539.95 462.2,346.9 802.7,346.9 812.12,356.32 812.12,416.32 723.45,505 653,505 570.3,587.7 570.3,1465.5
VDD_3p3V on L3_SIG1 "L3_SIG1-VDD_3p3V" (solid, remove dead copper, pour order 192): 1257.6,3763.17 1507.03,3763.17 1666.3,3922.44 1666.3,4033.29 1677.95,4044.94 2062.56,4044.94 2097.8,4009.7 2097.8,3958.8 2097.8,3660.6 1926.1,3488.9 1471.6,3488.9 1268.7,3286 224.8,3286 132.8,3378 132.8,4248.1 163.3,4278.6 475.7,4278.6 493,4261.3 493,3990.2 428.7,3925.9 428.7,3636.9 468.8,3596.8 615.3,3596.8 710.4,3691.9 904.9,3691.9 1034.8,3562 1161,3562 1209.6,3610.6 1209.6,3715.18
1P8V_CON on L3_SIG1 "L3_SIG1-1P8V_CON" (solid, remove dead copper, pour order 190): 1628.9,4016.1 1681.4,4068.6 1739.86,4068.6 1885.7,4214.44 1885.7,4445.8 1800.2,4531.3 1437.4,4531.3 1353.75,4447.65 1353.75,4123.12 1255.18,4023.5 580.5,4023.5 452,3895 452,3671.6 472.8,3650.8 622.8,3650.8 685.5,3713.5 915.7,3713.5 1040.1,3589.1 1146.87,3589.1 1170.2,3612.42 1170.2,3726.9 1254.7,3811.4 1475.65,3811.4 1628.9,3964.65
3P3V_CON on L3_SIG1 "L3_SIG1-3P3V_CON" (solid, remove dead copper, pour order 188): 1117.4,4078.6 1075.3,4120.7 1075.3,4818.6 1120.4,4863.7 1967.7,4863.7 2101.4,4730 2101.4,4269.32 2228.4,4142.32 2228.4,4083.85 2175.35,4030.8 2109.5,4030.8 1907,4233.3 1907,4502.1 1830.4,4578.7 1443.6,4578.7 1342.5,4477.6 1342.5,4173.67 1247.44,4078.6
1P2V_CON on L3_SIG1 "L3_SIG1-1P2V_CON" (solid, remove dead copper, pour order 186): 1979.2,3402.3 1645.94,3402.3 1620.54,3376.9 1620.54,3260.61 1651.95,3229.2 2178.6,3229.2 2304.22,3354.82 2304.22,3692.58 2509.6,3897.96 2509.6,4478.8 2492.8,4495.6 2170.5,4495.6 2152.5,4477.6 2152.5,4281 2255.8,4177.7 2255.8,3965.3 2117.5,3827 2117.5,3540.6
1P8V_FTDI on L3_SIG1 "L3_SIG1-1P8V_FTDI" (solid, remove dead copper, pour order 142): 602.35,757.9 602.35,606.75 663.7,545.4 896.6,545.4 982.33,459.67 1045.18,459.68 1082.3,496.8 1082.3,972.1 999.43,1054.97 644.72,1054.97 602.35,1012.6
VDD_1P8V_1 on L3_SIG1 "L3_SIG1-VDD_1P8V_1" (solid, remove dead copper, pour order 170): 954.41,1158.28 954.41,1302.25 1001.46,1349.3 1255.9,1349.3 1289.5,1315.7 1289.5,1163.8 1262.62,1136.92 975.77,1136.92
5V_USB on L3_SIG1 "L3_SIG1-5V_USB" (solid, remove dead copper, pour order 146): 394.77,1221.92 378.05,1238.65 147.25,1238.65 34.25,1125.65 34.25,474.65 371.7,137.2 859,137.2 869.5,147.7 869.5,284.2 850.5,303.2 457.4,303.2 247.7,512.9 247.7,1055.38 276,1083.68 373.68,1083.68 394.78,1104.78
3P3V_FTDI on L4_PWR1 "L4_PWR1-3P3V_FTDI" (solid, remove dead copper, pour order 158): 768.95,1484.65 1135.25,1484.65 1156.23,1463.67 1156.23,1441.25 1134.79,1419.81 1134.79,1279.86 1246.32,1168.33 1246.32,879.5 1262.32,863.5 1397.07,863.5 1443.88,816.7 1443.88,634.8 1421.88,612.8 1126.35,612.8 1028.1,711.05 160,711.05 125.35,745.7 125.35,1331.4 177.65,1383.7 400.93,1383.7 418.28,1366.35 418.28,1165.82 449,1135.1 922.67,1135.1 953.1,1165.53 953.1,1298.4 911.1,1340.4 771,1340.4 740.05,1371.35 740.05,1455.75
3P3V_VPLL on L4_PWR1 "L4_PWR1-3P3V_VPLL" (solid, remove dead copper, pour order 160): 504.92,1542.92 526,1521.85 526,1433.5 496.78,1404.28 156.47,1404.28 96.17,1343.97 96.17,726.45 142.83,679.8 892.62,679.8 974.7,597.72 974.7,285.3 936.53,247.12 54.88,247.12 -60.45,362.45 -60.45,1450.07 32.37,1542.9
VDD_1P8V_2 on L4_PWR1 "L4_PWR1-VDD_1P8V_2" (solid, remove dead copper, pour order 164): 3014.62,2773.13 3015.28,2773.13 3020.15,2778 3020.15,2787.52 3014.27,2793.4 2916.19,2793.4 2904.15,2805.44 2904.15,3339.48 2917.57,3352.9 3012.7,3352.9 3018.48,3358.68 3018.48,3368.55 3013.3,3373.73 2924.95,3373.73 2913.98,3384.7 2914.01,3527.69 2835.57,3606.12 1299.62,3606.12 1246.1,3659.65 1246.1,3764.2 1200.38,3809.93 829.62,3809.93 774.8,3755.1 774.8,3610.4 546.37,3381.97 546.38,1186.97 580.68,1152.68 924.25,1152.68 947.65,1176.07 947.65,1294.5 924.75,1317.4 754.05,1317.4 725.2,1346.25 725.2,1475.7 760.3,1510.8 1368.9,1510.8 1480.1,1622 1480.1,2555.77 1697.45,2773.13
VDD_1P8V_1 on L4_PWR1 "L4_PWR1-VDD_1P8V_1" (solid, remove dead copper, pour order 162): 1475.97,841.88 1255.9,1061.95 1255.9,1171.69 1144.7,1282.89 1144.7,1421.48 1199.72,1476.5 1446.95,1476.5 1488.43,1435.03 1488.43,1108.18 1538.15,1058.45 2360.97,1058.45 2678.2,1375.68 3030.88,1375.68 3062.2,1407 3062.2,1573.43 3023.35,1612.27 2941.2,1612.27 2935.15,1618.32 2935.15,1626.3 2941.9,1633.05 3029.4,1633.05 3067.25,1670.9 3067.25,1790.45 3049.23,1809.02 2883.52,1809.02 2866.3,1826.25 2866.3,1881.93 2885.88,1901.5 3027.32,1901.5 3067.25,1941.43 3067.25,2166.4 3043.07,2190.57 2937.18,2190.57 2931.7,2196.05 2931.7,2206.98 2938.9,2214.18 3042.43,2214.18 3069.25,2241 3069.25,2352.12 3037.98,2383.4 2909.07,2383.4 2891.82,2400.65 2891.82,2485.82 2916.62,2510.62 3088.98,2510.62 3146.51,2453.1 3146.51,2359.03 3168.62,2336.91 3323.89,2336.91 3597.47,2610.5 3597.48,3986.43 3352.23,4231.68 915.65,4231.68 715.18,4031.2 715.18,3640.68 629.4,3554.9 229.75,3554.9 156.9,3627.75 156.9,4635.1 411.55,4889.75 4011.4,4889.75 4358.05,4543.1 4358.05,965.65 3932.7,540.3 1530.97,540.3 1475.97,595.3
QSFP-DD_VCC_3P3V on L4_PWR1 "L4_PWR1-QSFP-DD_VCC_3P3V" (solid, remove dead copper, pour order 156): 2348.22,2551.73 1598.38,2551.75 1520.18,2473.55 1520.18,1130.9 1569.18,1081.9 2328.05,1081.9 2406.57,1160.42 2406.57,2493.37
VDD_1P2V_1 on L4_PWR1 "L4_PWR1-VDD_1P2V_1" (solid, remove dead copper, pour order 154): 3032.02,2223.02 3050.2,2241.2 3050.2,2300.58 3018.38,2332.4 2900.37,2332.4 2859.96,2372.8 2859.96,2513.46 2898.24,2551.74 3064.46,2551.74 3157,2459.2 3157,2367.52 3172.52,2352 3318.5,2352 3329.56,2363.06 3584.9,2618.4 3584.9,3940.07 3328.25,4196.73 1343.27,4196.72 1268.65,4122.1 1268.65,3728 1342.2,3654.45 1773.82,3654.45 1818.05,3698.68 1818.05,3834.8 1858.43,3875.18 3072,3875.18 3342.5,3604.67 3342.5,2840.12 3201.22,2698.85 2614.35,2698.85 2522.1,2606.6 2522.1,1418.47 2542.5,1398.07 3013.77,1398.07 3039.07,1423.38 3039.07,1575.73 3014,1600.8 2934.18,1600.8 2923.3,1611.68 2923.3,1635.57 2931.18,1643.45 3020.68,1643.45 3054.2,1676.98 3054.2,1766 3035.18,1785.02 2874.62,1785.02 2846.88,1812.77 2846.88,1898.05 2873.05,1924.23 3015.45,1924.23 3054.2,1962.98 3054.2,2158.32 3030.77,2181.75 2931.32,2181.75 2921.12,2191.95 2921.12,2212.57 2931.57,2223.02
VDD_1P2V_2 on L4_PWR1 "L4_PWR1-VDD_1P2V_2" (solid, remove dead copper, pour order 168): 1862.53,3854.68 1834.78,3826.93 1834.78,3687.23 1880.2,3641.8 2846.85,3641.8 2931,3557.65 2931,3393.88 2940.38,3384.5 3022.93,3384.5 3034.62,3372.8 3034.62,3353.95 3019.57,3338.9 2929.8,3338.9 2918.07,3327.18 2918.07,2819.05 2934.07,2803.05 3022.4,2803.05 3032.68,2792.77 3032.68,2775.4 3017.66,2760.39 2882.51,2760.39 2873.8,2751.67 2873.8,2722.07 2887.35,2708.52 3178.85,2708.52 3330.9,2860.57 3330.9,3584.62 3060.85,3854.68
GND on L5_GND2 "L5_GND2-GND" (solid, remove dead copper, pour order 176): 5361.7,4853.38 5249.82,4965.25 60.12,4965.25 -50.7,4854.43 -50.7,135.88 36.58,48.6 5109.05,48.6 5361.7,301.25

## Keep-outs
Keep-Out Layer:
  text ".Layer_Name" at -423,-1858.49 h60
